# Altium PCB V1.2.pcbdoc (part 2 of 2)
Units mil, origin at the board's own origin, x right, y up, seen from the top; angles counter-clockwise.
Board outline 3255.91 x 1171.26 mil, 2 copper layers (Top Layer, Bottom Layer), stack 2.757 mil thick; 72 components, 47 nets, 250 pads, 80 vias.
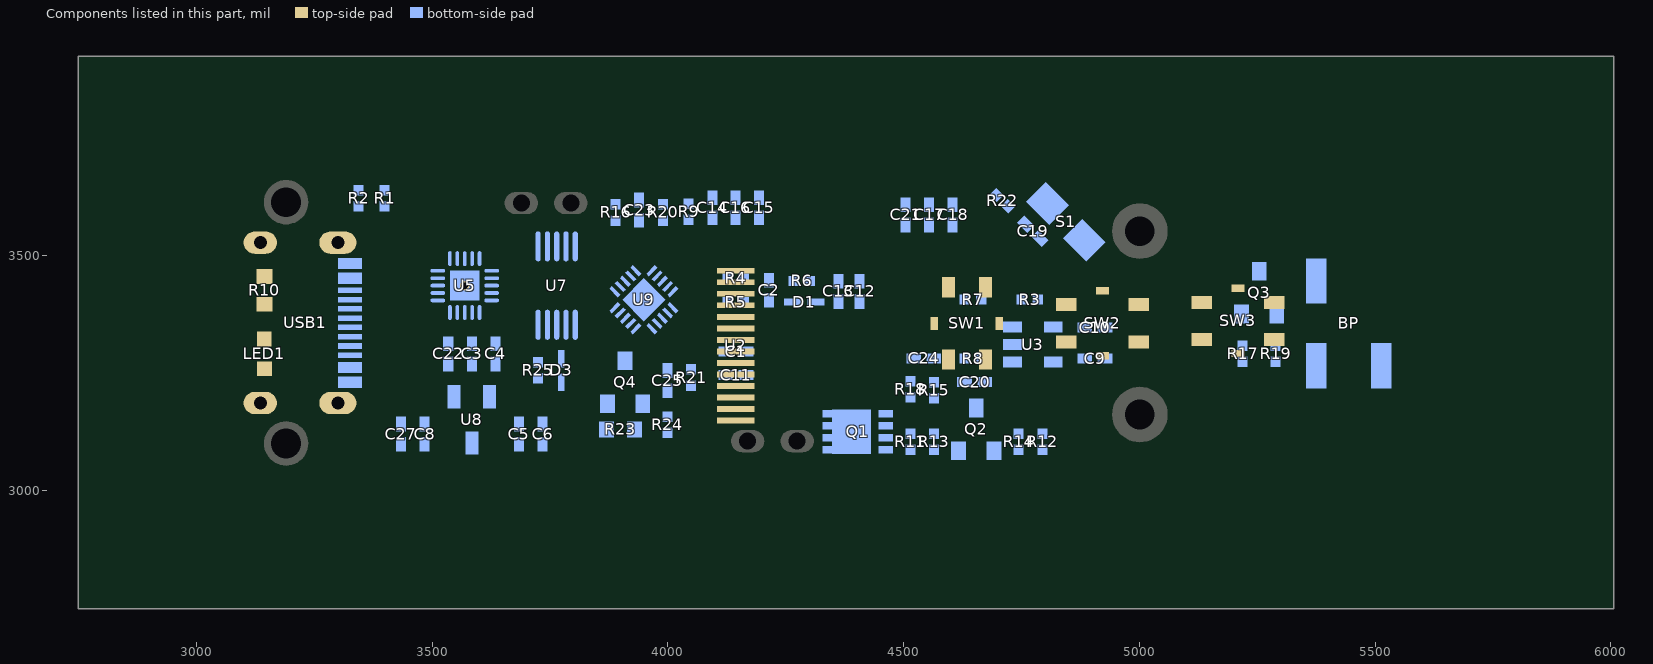
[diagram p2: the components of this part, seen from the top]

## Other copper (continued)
Bottom Layer:
  region net VBUS: 3324.32,3439.32 3421.32,3439.32 3421.32,3462.32 3324.32,3462.32
  region net VBUS: 3321.85,3250.32 3421.85,3250.32 3421.85,3273.32 3321.85,3273.32
  region net T12-OUTPUT: 4129.32,3075.32 4319.32,3075.32 4319.32,3130.32 4129.32,3130.32
  region net VBUS: 4449.32,3105.32 4489.32,3105.32 4489.32,3220.32 4449.32,3220.32
  region net T12-OUTPUT: 4304.32,3073.18 4379.52,3073.18 4379.52,3175.28 4304.32,3175.28
  region net CC1: 3291.18,3302.32 3300.18,3301.18 3300.18,3312.99 3291.18,3308.32
  region net DM: 3291.18,3323.77 3300.18,3320.86 3300.18,3332.67 3291.18,3329.77
  region net DP: 3291.18,3348.32 3291.18,3342.32 3300.18,3340.55 3300.18,3352.36
  region net DP: 3360.37,3349.46 3351.37,3352.36 3351.37,3340.55 3360.37,3343.46
  region net DM: 3291.18,3362.32 3300.18,3360.23 3300.18,3372.04 3291.18,3368.32
  region net DM: 3360.37,3369.14 3351.37,3372.04 3351.37,3360.23 3360.37,3363.14
  region net DP: 3291.18,3382.83 3300.18,3379.92 3300.18,3391.73 3291.18,3388.83
  region net CC2: 3291.18,3422.2 3300.18,3419.29 3300.18,3431.1 3291.18,3428.2
  region net VBUS: 3603.95,3314.78 3594.95,3322.28 3594.95,3301.28 3603.95,3308.78
  region net VBUS: 3588.06,3336.33 3582.06,3336.33 3574.56,3327.33 3594.95,3327.33
  region net +3.3V: 3701.19,3147.82 3701.19,3132.82 3723.69,3126.15 3723.69,3157.25
  region net +3.3V: 3767.45,3149.2 3744.95,3157.25 3744.95,3126.15 3767.45,3134.2
  region net VBUS: 3614.69,3314.78 3614.69,3308.78 3623.69,3301.28 3623.69,3322.28
  region net VBUS: 3631.32,3336.33 3623.82,3327.33 3644.82,3327.33 3637.32,3336.33
  region net +3.3V: 3679.32,3172.25 3673.69,3157.25 3694.95,3157.25 3689.32,3172.25
  region net +3.3V: 3654.32,3147.82 3654.32,3132.82 3673.69,3126.15 3673.69,3157.25
  region net +3.3V: 3717.45,3147.82 3673.69,3157.25 3673.69,3126.15 3717.45,3132.82
  region net +3.3V: 4890.32,3317.32 4899.87,3335.32 4868.76,3335.32 4878.32,3317.32
  region net +3.3V: 4890.32,3374.58 4878.32,3374.58 4868.76,3356.58 4899.87,3356.58
  region net +3.3V: 4890.32,3308.95 4878.32,3308.95 4868.76,3290.95 4899.87,3290.95
  region net $2N50518: 5288.06,3459.6 5288.06,3471.6 5270.06,3485.28 5270.06,3445.91
  region net $2N4674: 5297.72,3337.36 5307.47,3355.36 5275.97,3355.36 5285.72,3337.36
  region net $2N4674: 5260.69,3313.36 5260.69,3301.36 5278.69,3296.23 5278.69,3318.5
  region net $2N4674: 5297.72,3336.5 5285.72,3336.5 5278.69,3318.5 5299.95,3318.5
  region net $2N4674: 5247.95,3313.36 5229.95,3318.5 5229.95,3296.23 5247.95,3301.36
  region net BEEP: 5199.69,3270.28 5208.69,3262.78 5208.69,3283.78 5199.69,3276.28
  region net +3.3V: 4855.32,3266.92 4855.32,3278.92 4837.32,3284.72 4837.32,3261.12
  region net T12-ADC0: 4817.32,3368.52 4811.32,3368.52 4803.82,3359.52 4824.82,3359.52
  region net $2N9036: 4702.32,3269.92 4711.32,3262.42 4711.32,3283.42 4702.32,3275.92
  region net $2N8936: 4720.94,3368.52 4713.44,3359.52 4734.44,3359.52 4726.94,3368.52
  region net T12-OUTPUT: 4635.32,3215.32 4644.87,3219.69 4613.76,3219.69 4623.32,3215.32
  region net T12-OUTPUT: 4624.24,3258.95 4613.76,3240.95 4644.87,3240.95 4636.24,3258.95
  region net $2N7734: 4651.32,3146.91 4657.32,3146.91 4664.82,3155.91 4643.82,3155.91
  region net $2N8074: 4729.97,3079.64 4729.97,3094.64 4707.47,3104.73 4707.47,3065.36
  region net VBUS: 4488.69,3120.32 4503.69,3110.08 4503.69,3132.35 4488.69,3130.32
  region net $2N43776: 4481.19,3094.43 4481.19,3079.43 4503.69,3076 4503.69,3098.27
  region net $2N43776: 4547.45,3094.43 4503.69,3098.27 4503.69,3076 4547.45,3079.43
  region net $2N43776: 4531.19,3094.43 4531.19,3079.43 4553.69,3076 4553.69,3098.27
  region net $2N7734: 4583.95,3128.32 4574.95,3132.35 4574.95,3114.82 4583.95,3122.32
  region net $2N8074: 4777.45,3079.64 4777.45,3094.64 4754.95,3098.27 4754.95,3076
  region net $2N8074: 4711.19,3079.64 4733.69,3076 4733.69,3098.27 4711.19,3094.64
  region net T12-PWM: 4791.32,3141.35 4783.82,3132.35 4804.82,3132.35 4797.32,3141.35
  region net $2N8074: 4761.19,3079.64 4783.69,3076 4783.69,3098.27 4761.19,3094.64
  region net $2N8936: 4684.45,3408.32 4675.45,3415.82 4675.45,3394.82 4684.45,3402.32
  region net $2N9036: 4684.45,3277.32 4684.45,3283.32 4675.45,3290.82 4675.45,3269.82
  region net $2N9036: 4667.32,3299.95 4661.32,3299.95 4653.82,3290.95 4674.82,3290.95
  region net T12-OUTPUT: 4624.24,3251.69 4636.24,3251.69 4641.37,3269.69 4619.1,3269.69
  region net T12-ADC0: 4804.45,3408.32 4795.45,3415.82 4795.45,3394.82 4804.45,3402.32
  region net $2N8936: 4730.1,3408.32 4730.1,3402.32 4739.1,3394.82 4739.1,3415.82
  region net T12-ADC1: 3960.69,3579.28 3960.69,3567.28 3978.69,3562.15 3978.69,3584.42
  region net T12-ADC1: 3995.32,3544.15 3999.95,3562.15 3978.69,3562.15 3983.32,3544.15
  region net VBUS: 3883.32,3636.5 3878.69,3618.5 3899.95,3618.5 3895.32,3636.5
  region net T12-ADC1: 3917.95,3579.28 3899.95,3584.42 3899.95,3562.15 3917.95,3567.28
  region net T12-ADC1: 3910.69,3579.28 3910.69,3567.28 3949.95,3558.31 3949.95,3589.41
  region net T12-ADC1: 3967.95,3579.28 3949.95,3589.41 3949.95,3558.31 3967.95,3567.28
  region net CFG1: 3649.81,3422.57 3638.26,3423.51 3638.26,3415.64 3649.81,3416.57
  region net CC1: 3540.81,3511.82 3534.81,3511.82 3533.88,3504.27 3541.75,3504.27
  region net CFG3: 3556.56,3515.82 3550.56,3515.82 3549.62,3504.27 3557.5,3504.27
  region net CFG2: 3566.31,3515.82 3565.37,3504.27 3573.25,3504.27 3572.31,3515.82
  region net $2N15913: 3488.82,3416.57 3500.37,3415.64 3500.37,3423.51 3488.82,3422.57
  region net DP: 3488.82,3438.32 3488.82,3432.32 3500.37,3431.38 3500.37,3439.26
  region net CC2: 3488.82,3469.82 3488.82,3463.82 3500.37,3462.88 3500.37,3470.75
  region net DM: 3488.82,3454.07 3488.82,3448.07 3500.37,3447.13 3500.37,3455.01
  region net VBUS: 3588.06,3354.83 3589,3366.38 3581.13,3366.38 3582.06,3354.83
  region net $2N15913: 3514.69,3314.78 3514.69,3308.78 3523.69,3301.28 3523.69,3322.28
  region net CC1: 3418.95,3606.28 3409.95,3613.78 3409.95,3592.78 3418.95,3600.28
  region net CC2: 3347.32,3583.15 3354.82,3592.15 3333.82,3592.15 3341.32,3583.15
  region net CC2: 3324.69,3606.28 3324.69,3600.28 3333.69,3592.78 3333.69,3613.78
  region net $2N21899: 4190.33,3298.32 4181.33,3305.82 4181.33,3284.82 4190.33,3292.32
  region net $2N21898: 4098.3,3298.32 4098.3,3292.32 4107.3,3284.82 4107.3,3305.82
  region net $2N22011: 4190.33,3248.32 4181.33,3255.82 4181.33,3234.82 4190.33,3242.32
  region net $2N22010: 4098.3,3248.32 4098.3,3242.32 4107.3,3234.82 4107.3,3255.82
  region net +3.3V: 4381.19,3396.36 4396.19,3385.81 4396.19,3416.91 4381.19,3406.36
  region net +3.3V: 4435.36,3395.36 4435.36,3407.36 4417.45,3416.91 4417.45,3385.81
  region net +3.3V: 4387.45,3396.36 4387.45,3406.36 4372.45,3416.91 4372.45,3385.81
  region net +3.3V: 4336.19,3396.36 4351.19,3385.81 4351.19,3416.91 4336.19,3406.36
  region net +3.3V: 4296.32,3464.95 4290.22,3455.95 4309.82,3455.95 4302.32,3464.95
  region net +3.3V: 4314.32,3448.32 4312.49,3455.82 4312.49,3434.82 4314.32,3442.32
  region net $2N24051: 4261.32,3425.69 4267.32,3425.69 4274.82,3434.69 4256.14,3434.69
  region net $2N24051: 4233.95,3397.32 4233.95,3403.32 4224.95,3410.82 4224.95,3389.82
  region net +3.3V: 4164.36,3469.95 4158.36,3469.95 4150.86,3460.95 4171.86,3460.95
  region net +3.3V: 4158.36,3430.69 4164.36,3430.69 4171.86,3439.69 4150.86,3439.69
  region net OLED-SDA: 4107.14,3447.32 4116.14,3439.82 4116.14,3460.82 4107.14,3453.32
  region net +3.3V: 4158.36,3419.95 4150.86,3410.95 4171.86,3410.95 4164.36,3419.95
  region net OLED-SCL: 4130.28,3383.28 4137.78,3389.69 4116.78,3389.69 4124.28,3383.28
  region net $2N27198: 4041.32,3554.31 4047.32,3554.31 4054.82,3563.31 4033.82,3563.31
  region net $2N27436: 4091.32,3554.31 4097.32,3554.31 4104.82,3563.31 4083.82,3563.31
  region net $2N29185: 4173.52,3581.86 4173.52,3575.86 4182.52,3568.36 4182.52,3589.36
  region net $2N29185: 4141.32,3554.31 4147.32,3554.31 4153.78,3563.31 4133.82,3563.31
  region net $2N29185: 4162.78,3581.86 4153.78,3589.36 4153.78,3568.36 4162.78,3575.86
  region net NTC-ADC14: 4534.02,3235.87 4525.02,3243.37 4525.02,3222.37 4534.02,3229.87
  region net NTC-ADC14: 4561.39,3261.2 4567.39,3261.2 4574.89,3270.2 4553.89,3270.2
  region net NTC-ADC14: 4561.39,3300.46 4553.89,3291.46 4574.89,3291.46 4567.39,3300.46
  region net +3.3V: 4559.32,3169.69 4569.32,3169.69 4575.02,3184.69 4553.76,3184.69
  region net NTC-ADC14: 4544.76,3235.87 4544.76,3229.87 4553.76,3222.37 4553.76,3241.04
  region net NTC-ADC14: 4561.39,3250.04 4553.89,3241.04 4574.89,3241.04 4567.39,3250.04
  region net SLEEP_FLAG: 4739.66,3580.74 4740.72,3569.07 4755.57,3583.92 4743.9,3584.98
  region net SLEEP_FLAG: 4776.34,3576.05 4772.1,3580.3 4760.43,3579.24 4775.28,3564.39
  region net MCU-VCC: 3996.32,3279.87 3988.82,3270.87 4009.82,3270.87 4002.32,3279.87
  region net $2N43776: 4500.4,3094.43 4477.9,3094.8 4477.9,3079.06 4500.4,3079.43
  region net +3.3V: 5368.32,3205.32 5380.32,3205.32 5395.32,3217.52 5353.37,3217.52
  region net $2N50518: 5335.37,3459.6 5353.37,3444.6 5353.37,3486.6 5335.37,3471.6
  region net PW/MODEL: 4551.32,3539.31 4557.32,3539.31 4564.82,3548.31 4543.82,3548.31
  region net ADD: 4601.32,3539.31 4607.32,3539.31 4614.82,3548.31 4593.82,3548.31
  region net LESSEN: 4501.32,3539.31 4507.32,3539.31 4514.82,3548.31 4493.82,3548.31
  region net DP: 3710.42,3521.42 3710.42,3515.42 3719.42,3507.92 3719.42,3528.92
  region net DM: 3741.62,3558.43 3739.12,3544.82 3750.12,3544.82 3747.62,3558.43
  region net +3.3V: 3704.42,3355.32 3704.42,3345.32 3719.42,3332.82 3719.42,3367.82
  region net +3.3V: 3727.92,3392.23 3721.92,3392.23 3719.42,3378.62 3730.42,3378.62
  region net $2N81968: 3747.62,3312.21 3750.12,3325.82 3739.12,3325.82 3741.62,3312.21
  region net $2N81785: 3767.32,3312.21 3769.82,3325.82 3758.82,3325.82 3761.32,3312.21
  region net +3.3V: 3781.02,3392.23 3778.52,3378.62 3789.52,3378.62 3787.02,3392.23
  region net $2N65253: 4052.32,3277.5 4046.32,3277.5 4038.82,3268.5 4059.82,3268.5
  region net SLEEP_FLAG: 4780.2,3579.91 4791.87,3580.98 4777.02,3595.82 4775.96,3584.16
  region net +3.3V: 3862.16,3142.86 3877.16,3142.86 3887.66,3165.36 3856.17,3165.36
  region net +3.3V: 3864.41,3217.92 3856.17,3204.73 3887.66,3204.73 3879.41,3217.92
  region net MCU-VCC: 3912.31,3304.28 3906.31,3304.28 3898.81,3295.28 3919.81,3295.28
  region net MCU-VCC: 3934.06,3282.32 3934.06,3288.32 3925.06,3295.28 3925.06,3274.82
  region net $2N78998: 3933.36,3156.36 3939.36,3156.36 3946.86,3165.36 3930.97,3165.36
  region net +3.3V: 3831.28,3137.82 3831.28,3122.82 3853.78,3113.31 3853.78,3147.33
  region net +3.3V: 3862.16,3169.83 3853.78,3147.33 3885.53,3147.33 3877.16,3169.83
  region net $2N78998: 3933.36,3156.33 3925.86,3147.33 3944.85,3147.33 3939.36,3156.33
  region net $2N78998: 3953.85,3120.28 3953.85,3126.28 3944.85,3133.78 3944.85,3113.31
  region net $2N78998: 3979.69,3120.28 3988.69,3112.78 3988.69,3133.78 3979.69,3126.28
  region net VBUS: 3443.69,3108.78 3443.69,3088.78 3473.69,3083.23 3473.69,3114.33
  region net VBUS: 3524.95,3108.78 3494.95,3114.33 3494.95,3083.23 3524.95,3088.78
  region net VBUS: 3474.56,3108.78 3444.56,3114.33 3444.56,3083.23 3474.56,3088.78
  region net VBUS: 3394.32,3090.32 3423.3,3083.23 3423.3,3114.33 3394.32,3110.32
  region net $2N81968: 3727.32,3290.32 3721.32,3290.32 3713.82,3283.5 3734.82,3283.5
  region net MCU-TXD: 3721.32,3218.15 3727.32,3218.15 3734.82,3227.15 3713.82,3227.15
  region net +3.3V: 4309.32,3378.23 4319.32,3378.23 4331.82,3393.23 4296.82,3393.23
  region net +3.3V: 4327.32,3416.41 4321.32,3416.41 4313.82,3407.41 4332.62,3407.41
  region net +3.3V: 4347.62,3396.36 4347.62,3406.36 4332.62,3407.41 4332.62,3393.23
  region net $2N24051: 4261.32,3384.23 4267.32,3384.23 4274.82,3393.23 4253.82,3393.23
  region net $2N24051: 4237.01,3397.32 4246.01,3393.23 4246.01,3407.41 4237.01,3403.32
  region net $2N24051: 4261.32,3416.41 4253.82,3407.41 4274.82,3407.41 4267.32,3416.41
  region net MCU-RXD: 3771.32,3203.01 3777.32,3203.01 3781.4,3212.01 3767.23,3212.01
  region net $2N81785: 3777.32,3300.32 3771.32,3300.32 3767.23,3298.63 3781.4,3298.63
  region net VBUS: 3540.52,3108.78 3540.52,3088.78 3570.52,3076.52 3570.52,3125.72
  region net +3.3V: 3629.22,3172.92 3635.52,3174.92 3607.92,3174.92 3614.22,3172.92
  region net +3.3V: 4682.2,3638.2 4681.97,3627.82 4696.82,3642.67 4686.44,3642.44
  region net SLEEP_FLAG: 4733.48,3586.91 4737.72,3591.16 4736.66,3602.82 4721.81,3587.97
  region net SLEEP_FLAG: 4703.32,3593.56 4707.56,3589.32 4719.23,3590.38 4705.98,3603.63
  region net LESSEN: 4028.51,3374.91 4022.81,3381.94 4017.24,3376.37 4024.27,3370.67
  region net PW/MODEL: 4017.38,3363.78 4011.67,3370.8 4006.11,3365.24 4013.13,3359.54
  region net ADD: 4006.24,3352.64 4000.54,3359.67 3994.97,3354.1 4002,3348.4
  region net $2N65253: 3995.1,3341.5 3989.4,3348.53 3983.83,3342.96 3990.86,3337.26
  region net MCU-VCC: 3983.97,3330.37 3978.26,3337.39 3972.7,3331.83 3979.72,3326.12
  region net MCU-VCC: 3918.91,3326.12 3925.94,3331.83 3920.37,3337.39 3914.67,3330.37
  region net MCU-RXD: 3896.64,3348.4 3903.66,3354.1 3898.1,3359.67 3892.39,3352.64
  region net MCU-TXD: 3885.5,3359.54 3892.53,3365.24 3886.96,3370.8 3881.26,3363.78
  region net SLEEP_FLAG: 3874.36,3370.67 3881.39,3376.37 3875.82,3381.94 3870.12,3374.91
  region net CFG1: 3872.65,3433.2 3875.82,3428.7 3881.39,3434.27 3876.89,3437.44
  region net CFG2: 3881.26,3446.86 3886.96,3439.84 3892.53,3445.4 3885.5,3451.11
  region net CFG3: 3892.39,3458 3898.1,3450.97 3903.66,3456.54 3896.64,3462.24
  region net NTC-ADC14: 3907.77,3473.38 3903.53,3469.14 3909.23,3462.11 3914.8,3467.68
  region net BEEP: 3914.67,3480.27 3920.37,3473.25 3925.94,3478.82 3918.91,3484.52
  region net T12-ADC0: 3979.72,3484.52 3972.7,3478.82 3978.26,3473.25 3983.97,3480.27
  region net OLED-SDA: 3990.86,3473.38 3983.83,3467.68 3989.4,3462.11 3995.1,3469.14
  region net OLED-SCL: 4002,3462.24 3994.97,3456.54 4000.54,3450.97 4006.24,3458
  region net T12-PWM: 4013.13,3451.11 4006.11,3445.4 4011.67,3439.84 4017.38,3446.86
  region net T12-ADC1: 4021.74,3437.44 4017.24,3434.27 4022.81,3428.7 4025.99,3433.2
  region net $2N9036: 4676.45,3324.52 4683.95,3333.52 4662.95,3333.52 4670.45,3324.52
  region net $2N29185: 4151.82,3541.94 4147.32,3552.32 4141.32,3552.32 4136.82,3541.94
  region net $2N27436: 4101.82,3541.94 4097.32,3552.32 4091.32,3552.32 4086.82,3541.94
  region net $2N27198: 4051.82,3541.94 4047.32,3552.32 4041.32,3552.32 4036.82,3541.94
  region net $2N24051: 4271.82,3381.94 4267.32,3392.32 4261.32,3392.32 4256.82,3381.94
  region net +3.3V: 4321.82,3381.94 4319.32,3392.32 4309.32,3392.32 4306.82,3381.94
  region net CC1: 3276.82,3628.71 3281.32,3618.32 3287.32,3618.32 3291.82,3628.71
  region net CC1: 3441.31,3611.31 3431.75,3606.28 3433,3600.28 3444.37,3596.63
  region net CC1: 3441.82,3598.71 3446.32,3588.32 3452.32,3588.32 3456.82,3598.71
  region net DM: 3285.93,3357.82 3296.32,3362.32 3296.32,3368.32 3285.93,3372.82
  region net DM: 3286.95,3318.86 3296.73,3323.77 3295.85,3329.77 3284.78,3333.7
  region net DP: 3538.8,3542.13 3547.79,3547.32 3544.33,3553.32 3531.3,3555.12
  region net DP: 3459.3,3404.69 3463.46,3415.22 3459.22,3419.46 3448.69,3415.3
  region net DP: 3439.34,3405.95 3435.17,3395.42 3439.42,3391.18 3449.94,3395.34
  region net DM: 3510.93,3557.82 3521.32,3562.32 3521.32,3568.32 3510.93,3572.82
  region net DM: 3444.34,3450.95 3440.17,3440.42 3444.42,3436.18 3454.94,3440.34
  region net DM: 3461.47,3443.34 3471.53,3448.07 3471.08,3454.07 3460.35,3458.29
  region net VBUS: 3644.34,3360.95 3640.17,3350.42 3644.42,3346.18 3654.94,3350.34
  region net MCU-TXD: 3816.82,3226.94 3812.32,3237.32 3806.32,3237.32 3801.82,3226.94
  region net MCU-TXD: 3731.82,3201.94 3727.32,3212.32 3721.32,3212.32 3716.82,3201.94
  region net OLED-SDA: 4101.82,3401.94 4097.32,3412.32 4091.32,3412.32 4086.82,3401.94
  region net OLED-SCL: 4076.3,3365.52 4089.33,3367.32 4092.79,3373.32 4083.8,3378.51
  region net OLED-SCL: 4081.82,3381.94 4077.32,3392.32 4071.32,3392.32 4066.82,3381.94
  region net VBUS: 3881.82,3638.71 3883.32,3628.32 3895.32,3628.32 3896.82,3638.71
  region net T12-ADC1: 3996.82,3541.94 3995.32,3552.32 3983.32,3552.32 3981.82,3541.94
  region net BEEP: 3906.82,3518.71 3911.32,3508.32 3917.32,3508.32 3921.82,3518.71
  region net NTC-ADC14: 3876.82,3518.71 3881.32,3508.32 3887.32,3508.32 3891.82,3518.71
  region net T12-ADC1: 4042.7,3442.82 4032.32,3438.32 4032.32,3432.32 4042.7,3427.82
  region net T12-PWM: 4021.3,3461.3 4012.88,3450.86 4014.36,3443.85 4024.39,3446.62
  region net SLEEP_FLAG: 3850.93,3362.82 3861.32,3367.32 3861.32,3373.32 3850.93,3377.82
  region net T12-OUTPUT: 4614.3,3189.69 4620.58,3198.1 4612.1,3206.58 4603.69,3200.3
  region net BEEP: 4250.93,3572.82 4261.32,3577.32 4261.32,3583.32 4250.93,3587.82
  region net T12-PWM: 4786.82,3153.71 4791.32,3143.32 4797.32,3143.32 4801.82,3153.71
  region net +3.3V: 5126.82,3256.49 5125.32,3266.88 5113.32,3266.88 5111.82,3256.49
  region net +3.3V: 5111.82,3243.27 5113.32,3232.88 5125.32,3232.88 5126.82,3243.27
  region net +3.3V: 4571.82,3166.94 4569.32,3177.32 4559.32,3177.32 4556.82,3166.94
  region net LESSEN: 4494.34,3425.95 4490.17,3415.42 4494.42,3411.18 4504.94,3415.34
  region net ADD: 4541.82,3418.71 4546.32,3408.32 4552.32,3408.32 4556.82,3418.71
  region net PW/MODEL: 4514.34,3405.95 4510.17,3395.42 4514.42,3391.18 4524.94,3395.34
  region net LESSEN: 4511.82,3526.94 4507.32,3537.32 4501.32,3537.32 4496.82,3526.94
  region net PW/MODEL: 4561.82,3526.94 4557.32,3537.32 4551.32,3537.32 4546.82,3526.94
  region net ADD: 4611.82,3526.94 4607.32,3537.32 4601.32,3537.32 4596.82,3526.94
  region net T12-ADC0: 4424.94,3505.3 4414.42,3509.46 4410.17,3505.22 4414.34,3494.69
  region net T12-ADC0: 4485.93,3447.82 4496.32,3452.32 4496.32,3458.32 4485.93,3462.82
  region net NTC-ADC14: 4460.93,3287.82 4471.32,3292.32 4471.32,3298.32 4460.93,3302.82
  region net SLEEP_FLAG: 4699.3,3574.69 4703.46,3585.22 4699.22,3589.46 4688.69,3585.3
  region net +3.3V: 4459.94,3555.3 4449.42,3559.46 4445.17,3555.22 4449.34,3544.69
  region net +3.3V: 4334.94,3495.3 4326.44,3497.44 4322.2,3493.2 4324.34,3484.69
  region net $2N22010: 4094.3,3234.69 4096.44,3243.2 4092.2,3247.44 4083.69,3245.3
  region net $2N22011: 4214.94,3235.3 4204.42,3239.46 4200.17,3235.22 4204.34,3224.69
  region net $2N21898: 4070.93,3287.82 4081.32,3292.32 4081.32,3298.32 4070.93,3302.82
  region net $2N21899: 4239.94,3295.3 4231.44,3297.44 4227.2,3293.2 4229.34,3284.69

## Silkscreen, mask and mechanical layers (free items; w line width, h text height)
Top Silkscreen Layer:
  lines w10 net "": 3090,3356.3 3248.05,3356.3 3248.45,3356.7 ; 4568.42,3290.32 4568.42,3292.82 4700.22,3424.62 ; 4568.42,3424.22 4700.22,3292.42 4700.22,3290.32 ; 4856.28,3421.22 4988.08,3289.42 4990.58,3289.42 ; 4856.68,3289.42 4988.48,3421.22 4990.58,3421.22 ; 5144.32,3289.42 5146.42,3289.42 5278.22,3421.22 ; 5144.32,3421.22 5146.82,3421.22 5278.62,3289.42
Mechanical 6:
  lines w1.97 net "": 3662.83,3604.33 3820.31,3604.33 3820.31,3612.2 3662.83,3612.2 3662.83,3604.33
  lines w3.94 net "": 4143.15,3100.39 4143.15,3041.34 3090,3041.34 3090,3100.39 4143.15,3100.39 ; 4143.15,3100.39 4300.63,3100.39 4300.63,3108.27 4143.15,3108.27 4143.15,3100.39 ; 3090,3612.2 3662.83,3612.2 3662.83,3671.26 3090,3671.26 3090,3612.2
  lines w10 net "": 3000,3356.3 5755.91,3356.3 ; 4698.3,3424.62 4855.78,3424.62 ; 4987.58,3424.62 5145.06,3424.62 ; 5001.3,3161.81 5099.72,3161.81 5099.72,3063.39 5001.3,3063.39 5001.3,3161.81 ; 5001.3,3161.81 5001.3,3550.79 ; 5001.3,3550.79 5099.72,3550.79 5099.72,3649.21 5001.3,3649.21 5001.3,3550.79 ; 3090,3041.34 3190.39,3041.34 3190.39,3100.39 3090,3100.39 3090,3041.34 ; 3090,3612.2 3190.39,3612.2 3190.39,3671.26 3090,3671.26 3090,3612.2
